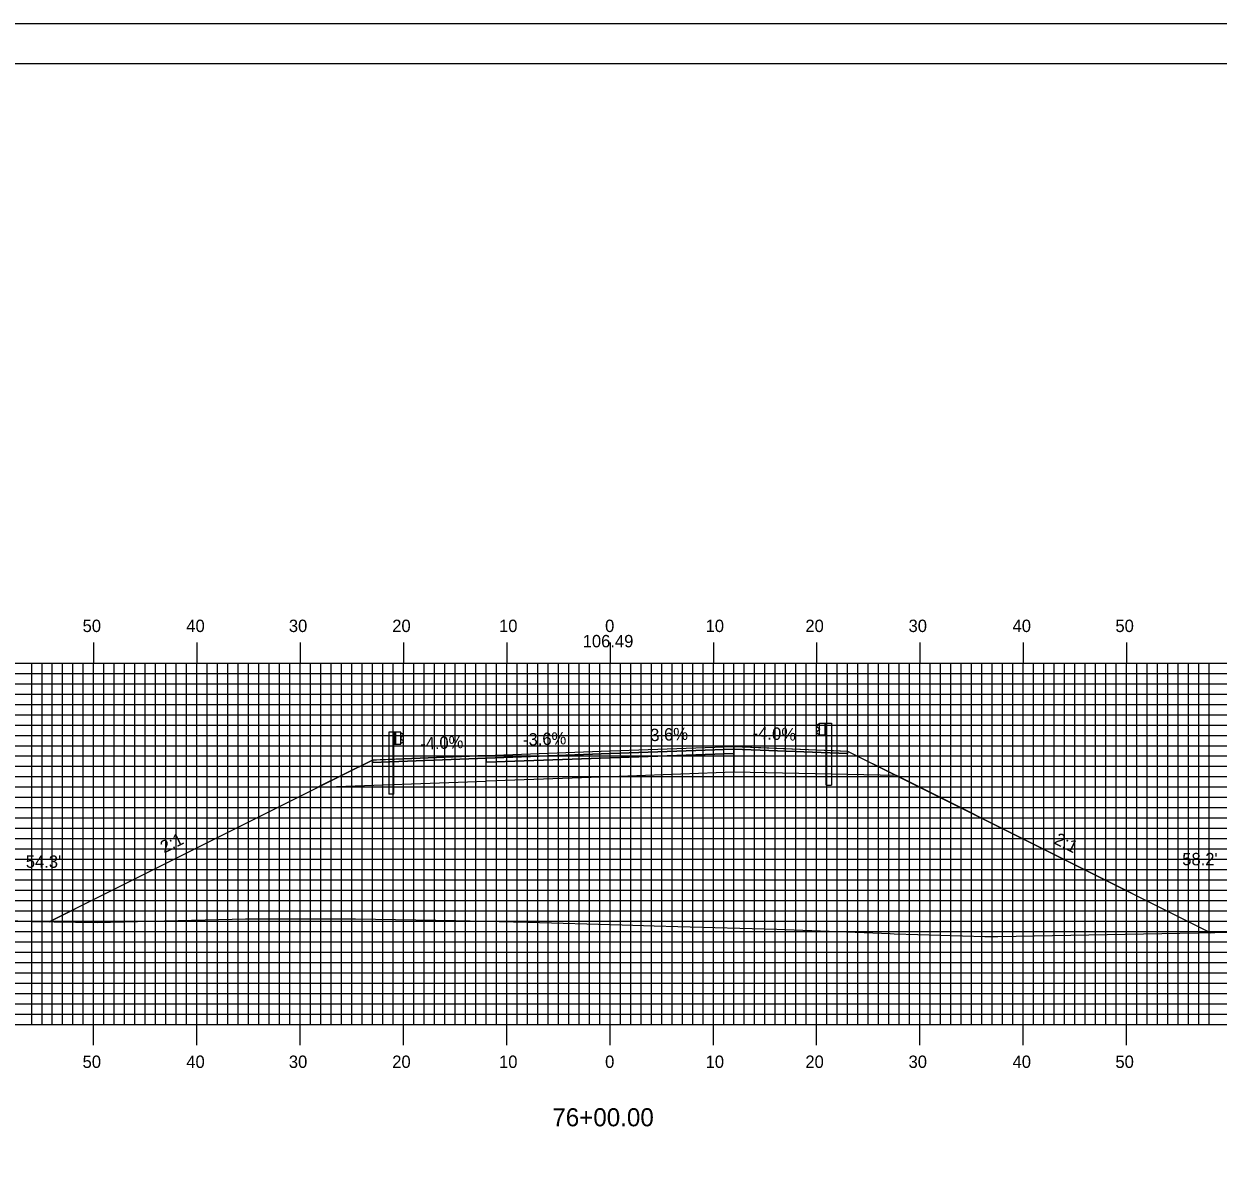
# Model space of a CAD drawing. Extents: x 1761397 to 1761741, y 442591 to 442811.
# Drawn here: x 1761506.5 to 1761622.1, y 442700.5 to 442810.5 of the extents above; entities that cross this region are included whole.
import ezdxf

# ---------------------------------------------------------------- set-up
doc = ezdxf.new("R2010")
doc.units = 0
for name, color, linetype in [('ANNOTATION', 7, 'Continuous'), ('BORDER', 7, 'Continuous'), ('D_Guardrail_Beam_Lt', 7, 'Continuous'), ('D_Guardrail_Beam_Rt', 7, 'Continuous'), ('D_Roadway_Centerline', 7, 'Continuous'), ('D_Roadway_Centerline_Text', 7, 'Continuous'), ('D_Roadway_Edge_Shoulder', 7, 'Continuous'), ('D_Roadway_Edge_TW', 7, 'Continuous'), ('D_Roadway_Pavement', 7, 'Continuous'), ('D_Roadway_SlopeLines', 7, 'Continuous'), ('D_Roadway_SubGrade', 7, 'Continuous'), ('D_Text_Standard', 7, 'Continuous'), ('H_V ANNOTATION', 7, 'Continuous'), ('MAJOR', 7, 'Continuous'), ('MINOR', 7, 'Continuous'), ('PLOT BOUNDARY', 7, 'Continuous'), ('S_Roadway_Centerline', 7, 'Continuous')]:
    doc.layers.add(name, color=color, linetype=linetype)

msp = doc.modelspace()

# ---------------------------------------------------------------- linework, layer by layer
at = {"layer": 'BORDER'}
msp.add_lwpolyline([(1761413.64, 442596.67), (1761733.64, 442596.67), (1761733.64, 442806.67), (1761413.64, 442806.67)], close=True, dxfattribs=at)
at = {"layer": 'D_Guardrail_Beam_Lt'}
for p, q in [((1761541.81, 442741.99), (1761541.81, 442735.99)), ((1761542.28, 442741.99), (1761541.81, 442741.99)), ((1761542.97, 442741.99), (1761542.28, 442741.99)), ((1761542.28, 442741.99), (1761542.28, 442740.82)), ((1761542.34, 442741.99), (1761542.34, 442740.82)), ((1761542.45, 442741.99), (1761542.45, 442740.82)), ((1761542.97, 442740.82), (1761542.97, 442741.99)), ((1761542.97, 442741.9), (1761543.04, 442741.89)), ((1761542.97, 442741.44), (1761542.97, 442741.37)), ((1761543.2, 442741.64), (1761543.01, 442741.5)), ((1761543.01, 442741.3), (1761543.2, 442741.17)), ((1761543.06, 442741.88), (1761543.2, 442741.78)), ((1761542.28, 442740.82), (1761542.97, 442740.82)), ((1761542.3, 442735.99), (1761542.3, 442740.82)), ((1761543.04, 442740.92), (1761542.97, 442740.9)), ((1761543.2, 442741.02), (1761543.06, 442740.92)), ((1761542.3, 442735.99), (1761541.81, 442735.99))]:
    msp.add_line(p, q, dxfattribs=at)
for centre, major_axis, start_param, end_param in [((1761543.05, 442741.44), (-0.0789, 0), 5.323254, 6.283185), ((1761543.05, 442741.37), (-0.0789, 0), 6.283185, 7.243116), ((1761543.03, 442741.85), (0.0417, 0), 0.959931, 1.376053), ((1761543.15, 442741.71), (0.0877, 0), 5.323254, 7.243116), ((1761543.15, 442741.1), (0.0877, 0), 5.323254, 7.243116), ((1761543.03, 442740.96), (0.0417, 0), 4.907132, 5.323254)]:
    msp.add_ellipse(centre, major_axis=major_axis, ratio=0.995501, start_param=start_param, end_param=end_param, dxfattribs=at)
at = {"layer": 'D_Guardrail_Beam_Rt'}
for p, q in [((1761583.42, 442742.75), (1761583.28, 442742.65)), ((1761583.28, 442742.5), (1761583.47, 442742.37)), ((1761583.51, 442742.77), (1761583.44, 442742.75)), ((1761583.51, 442742.85), (1761584.2, 442742.85)), ((1761583.51, 442741.68), (1761583.51, 442742.85)), ((1761584.03, 442742.85), (1761584.03, 442741.68)), ((1761584.14, 442742.85), (1761584.14, 442741.68)), ((1761584.2, 442742.85), (1761584.67, 442742.85)), ((1761584.2, 442742.85), (1761584.2, 442741.68)), ((1761584.67, 442742.85), (1761584.67, 442736.85)), ((1761583.47, 442742.17), (1761583.28, 442742.03)), ((1761583.28, 442741.89), (1761583.42, 442741.79)), ((1761583.44, 442741.78), (1761583.51, 442741.77)), ((1761583.51, 442742.3), (1761583.51, 442742.23)), ((1761584.2, 442741.68), (1761583.51, 442741.68)), ((1761584.18, 442736.85), (1761584.18, 442741.68)), ((1761584.18, 442736.85), (1761584.67, 442736.85))]:
    msp.add_line(p, q, dxfattribs=at)
for centre, major_axis, start_param, end_param in [((1761583.33, 442742.57), (-0.0877, 0), 5.323254, 7.243116), ((1761583.44, 442742.71), (-0.0417, 0), 4.907132, 5.323254), ((1761583.43, 442742.3), (0.0789, 0), 0, 0.959931), ((1761583.33, 442741.96), (-0.0877, 0), 5.323254, 7.243116), ((1761583.44, 442741.82), (-0.0417, 0), 0.959931, 1.376053), ((1761583.43, 442742.23), (0.0789, 0), 5.323254, 6.283185)]:
    msp.add_ellipse(centre, major_axis=major_axis, ratio=0.995501, start_param=start_param, end_param=end_param, dxfattribs=at)
at = {"layer": 'D_Roadway_Centerline'}
msp.add_lwpolyline([(1761508.92, 442723.62), (1761508.92, 442723.62), (1761514.06, 442726.19), (1761534.93, 442736.63), (1761534.95, 442736.64), (1761534.95, 442736.64), (1761540.24, 442739.28), (1761540.64, 442739.3), (1761543.24, 442739.4), (1761543.24, 442739.4), (1761551.24, 442739.72), (1761563.24, 442740.16), (1761563.24, 442740.16), (1761575.24, 442740.59), (1761577.85, 442740.48), (1761583.23, 442740.27), (1761583.24, 442740.27), (1761584.88, 442740.2), (1761586.24, 442740.15), (1761590.99, 442737.77), (1761590.99, 442737.77), (1761591, 442737.77), (1761621.41, 442722.56)], dxfattribs=at)
at = {"layer": 'D_Roadway_Edge_Shoulder'}
for points in [[(1761575.24, 442740.59), (1761583.24, 442740.27), (1761583.24, 442740.27), (1761586.24, 442740.15), (1761586.24, 442739.9), (1761575.24, 442740.34)], [(1761551.24, 442739.72), (1761543.24, 442739.4), (1761543.24, 442739.4), (1761540.24, 442739.28), (1761540.24, 442739.03), (1761551.24, 442739.47)]]:
    msp.add_lwpolyline(points, close=True, dxfattribs=at)
at = {"layer": 'D_Roadway_Edge_TW'}
msp.add_lwpolyline([(1761551.24, 442739.47), (1761551.24, 442739.72), (1761563.24, 442740.16), (1761575.24, 442740.59), (1761575.24, 442740.34), (1761563.24, 442739.91)], close=True, dxfattribs=at)
at = {"layer": 'D_Roadway_Pavement'}
msp.add_lwpolyline([(1761551.24, 442739.06), (1761551.24, 442739.47), (1761563.24, 442739.91), (1761575.24, 442740.34), (1761575.24, 442739.92), (1761563.24, 442739.49)], close=True, dxfattribs=at)
for points in [[(1761575.24, 442740.34), (1761575.24, 442739.92)], [(1761551.24, 442739.47), (1761551.24, 442739.06)]]:
    msp.add_lwpolyline(points, dxfattribs=at)
at = {"layer": 'D_Roadway_SlopeLines'}
for points in [[(1761586.24, 442740.15), (1761621.41, 442722.56)], [(1761540.24, 442739.28), (1761508.92, 442723.62)]]:
    msp.add_lwpolyline(points, dxfattribs=at)
at = {"layer": 'D_Roadway_SubGrade'}
for points in [[(1761551.24, 442737.22), (1761551.24, 442739.47), (1761551.24, 442739.06), (1761563.24, 442739.49), (1761575.24, 442739.92), (1761575.24, 442740.34), (1761575.24, 442738.09), (1761563.24, 442737.66)], [(1761575.24, 442739.92), (1761575.24, 442740.34), (1761586.24, 442739.9), (1761586.24, 442740.15), (1761590.99, 442737.77), (1761575.24, 442738.09)], [(1761551.24, 442739.06), (1761551.24, 442739.47), (1761540.24, 442739.03), (1761540.24, 442739.28), (1761534.95, 442736.64), (1761551.24, 442737.22)]]:
    msp.add_lwpolyline(points, close=True, dxfattribs=at)
at = {"layer": 'MAJOR'}
for p, q in [((1761513.24, 442750.67), (1761513.24, 442748.67)), ((1761523.24, 442750.67), (1761523.24, 442748.67)), ((1761533.24, 442750.67), (1761533.24, 442748.67)), ((1761543.24, 442750.67), (1761543.24, 442748.67)), ((1761553.24, 442750.67), (1761553.24, 442748.67)), ((1761563.24, 442750.67), (1761563.24, 442748.67)), ((1761573.24, 442750.67), (1761573.24, 442748.67)), ((1761583.24, 442750.67), (1761583.24, 442748.67)), ((1761593.24, 442750.67), (1761593.24, 442748.67)), ((1761603.24, 442750.67), (1761603.24, 442748.67)), ((1761613.24, 442750.67), (1761613.24, 442748.67)), ((1761423.24, 442748.67), (1761703.24, 442748.67)), ((1761423.24, 442748.67), (1761703.24, 442748.67)), ((1761513.24, 442713.67), (1761513.24, 442748.67)), ((1761523.24, 442713.67), (1761523.24, 442748.67)), ((1761533.24, 442713.67), (1761533.24, 442748.67)), ((1761543.24, 442713.67), (1761543.24, 442748.67)), ((1761553.24, 442713.67), (1761553.24, 442748.67)), ((1761563.24, 442713.67), (1761563.24, 442748.67)), ((1761573.24, 442713.67), (1761573.24, 442748.67)), ((1761583.24, 442713.67), (1761583.24, 442748.67)), ((1761593.24, 442713.67), (1761593.24, 442748.67)), ((1761603.24, 442713.67), (1761603.24, 442748.67)), ((1761613.24, 442713.67), (1761613.24, 442748.67)), ((1761423.24, 442743.67), (1761703.24, 442743.67)), ((1761423.24, 442738.67), (1761703.24, 442738.67)), ((1761423.24, 442733.67), (1761703.24, 442733.67)), ((1761423.24, 442728.67), (1761703.24, 442728.67)), ((1761423.24, 442723.67), (1761703.24, 442723.67)), ((1761423.24, 442718.67), (1761703.24, 442718.67)), ((1761423.24, 442713.67), (1761703.24, 442713.67)), ((1761423.24, 442713.67), (1761703.24, 442713.67)), ((1761513.24, 442711.66), (1761513.24, 442713.67)), ((1761523.24, 442711.66), (1761523.24, 442713.67)), ((1761533.24, 442711.66), (1761533.24, 442713.67)), ((1761543.24, 442711.66), (1761543.24, 442713.67)), ((1761553.24, 442711.66), (1761553.24, 442713.67)), ((1761563.24, 442711.66), (1761563.24, 442713.67)), ((1761573.24, 442711.66), (1761573.24, 442713.67)), ((1761583.24, 442711.66), (1761583.24, 442713.67)), ((1761593.24, 442711.66), (1761593.24, 442713.67)), ((1761603.24, 442711.66), (1761603.24, 442713.67)), ((1761613.24, 442711.66), (1761613.24, 442713.67))]:
    msp.add_line(p, q, dxfattribs=at)
at = {"layer": 'MINOR'}
for p, q in [((1761507.24, 442713.67), (1761507.24, 442748.67)), ((1761508.24, 442713.67), (1761508.24, 442748.67)), ((1761509.24, 442713.67), (1761509.24, 442748.67)), ((1761510.24, 442713.67), (1761510.24, 442748.67)), ((1761511.24, 442713.67), (1761511.24, 442748.67)), ((1761512.24, 442713.67), (1761512.24, 442748.67)), ((1761514.24, 442713.67), (1761514.24, 442748.67)), ((1761515.24, 442713.67), (1761515.24, 442748.67)), ((1761516.24, 442713.67), (1761516.24, 442748.67)), ((1761517.24, 442713.67), (1761517.24, 442748.67)), ((1761518.24, 442713.67), (1761518.24, 442748.67)), ((1761519.24, 442713.67), (1761519.24, 442748.67)), ((1761520.24, 442713.67), (1761520.24, 442748.67)), ((1761521.24, 442713.67), (1761521.24, 442748.67)), ((1761522.24, 442713.67), (1761522.24, 442748.67)), ((1761524.24, 442713.67), (1761524.24, 442748.67)), ((1761525.24, 442713.67), (1761525.24, 442748.67)), ((1761526.24, 442713.67), (1761526.24, 442748.67)), ((1761527.24, 442713.67), (1761527.24, 442748.67)), ((1761528.24, 442713.67), (1761528.24, 442748.67)), ((1761529.24, 442713.67), (1761529.24, 442748.67)), ((1761530.24, 442713.67), (1761530.24, 442748.67)), ((1761531.24, 442713.67), (1761531.24, 442748.67)), ((1761532.24, 442713.67), (1761532.24, 442748.67)), ((1761534.24, 442713.67), (1761534.24, 442748.67)), ((1761535.24, 442713.67), (1761535.24, 442748.67)), ((1761536.24, 442713.67), (1761536.24, 442748.67)), ((1761537.24, 442713.67), (1761537.24, 442748.67)), ((1761538.24, 442713.67), (1761538.24, 442748.67)), ((1761539.24, 442713.67), (1761539.24, 442748.67)), ((1761540.24, 442713.67), (1761540.24, 442748.67)), ((1761541.24, 442713.67), (1761541.24, 442748.67)), ((1761542.24, 442713.67), (1761542.24, 442748.67)), ((1761544.24, 442713.67), (1761544.24, 442748.67)), ((1761545.24, 442713.67), (1761545.24, 442748.67)), ((1761546.24, 442713.67), (1761546.24, 442748.67)), ((1761547.24, 442713.67), (1761547.24, 442748.67)), ((1761548.24, 442713.67), (1761548.24, 442748.67)), ((1761549.24, 442713.67), (1761549.24, 442748.67)), ((1761550.24, 442713.67), (1761550.24, 442748.67)), ((1761551.24, 442713.67), (1761551.24, 442748.67)), ((1761552.24, 442713.67), (1761552.24, 442748.67)), ((1761554.24, 442713.67), (1761554.24, 442748.67)), ((1761555.24, 442713.67), (1761555.24, 442748.67)), ((1761556.24, 442713.67), (1761556.24, 442748.67)), ((1761557.24, 442713.67), (1761557.24, 442748.67)), ((1761558.24, 442713.67), (1761558.24, 442748.67)), ((1761559.24, 442713.67), (1761559.24, 442748.67)), ((1761560.24, 442713.67), (1761560.24, 442748.67)), ((1761561.24, 442713.67), (1761561.24, 442748.67)), ((1761562.24, 442713.67), (1761562.24, 442748.67)), ((1761564.24, 442713.67), (1761564.24, 442748.67)), ((1761565.24, 442713.67), (1761565.24, 442748.67)), ((1761566.24, 442713.67), (1761566.24, 442748.67)), ((1761567.24, 442713.67), (1761567.24, 442748.67)), ((1761568.24, 442713.67), (1761568.24, 442748.67)), ((1761569.24, 442713.67), (1761569.24, 442748.67)), ((1761570.24, 442713.67), (1761570.24, 442748.67)), ((1761571.24, 442713.67), (1761571.24, 442748.67)), ((1761572.24, 442713.67), (1761572.24, 442748.67)), ((1761574.24, 442713.67), (1761574.24, 442748.67)), ((1761575.24, 442713.67), (1761575.24, 442748.67)), ((1761576.24, 442713.67), (1761576.24, 442748.67)), ((1761577.24, 442713.67), (1761577.24, 442748.67)), ((1761578.24, 442713.67), (1761578.24, 442748.67)), ((1761579.24, 442713.67), (1761579.24, 442748.67)), ((1761580.24, 442713.67), (1761580.24, 442748.67)), ((1761581.24, 442713.67), (1761581.24, 442748.67)), ((1761582.24, 442713.67), (1761582.24, 442748.67)), ((1761584.24, 442713.67), (1761584.24, 442748.67)), ((1761585.24, 442713.67), (1761585.24, 442748.67)), ((1761586.24, 442713.67), (1761586.24, 442748.67)), ((1761587.24, 442713.67), (1761587.24, 442748.67)), ((1761588.24, 442713.67), (1761588.24, 442748.67)), ((1761589.24, 442713.67), (1761589.24, 442748.67)), ((1761590.24, 442713.67), (1761590.24, 442748.67)), ((1761591.24, 442713.67), (1761591.24, 442748.67)), ((1761592.24, 442713.67), (1761592.24, 442748.67)), ((1761594.24, 442713.67), (1761594.24, 442748.67)), ((1761595.24, 442713.67), (1761595.24, 442748.67)), ((1761596.24, 442713.67), (1761596.24, 442748.67)), ((1761597.24, 442713.67), (1761597.24, 442748.67)), ((1761598.24, 442713.67), (1761598.24, 442748.67)), ((1761599.24, 442713.67), (1761599.24, 442748.67)), ((1761600.24, 442713.67), (1761600.24, 442748.67)), ((1761601.24, 442713.67), (1761601.24, 442748.67)), ((1761602.24, 442713.67), (1761602.24, 442748.67)), ((1761604.24, 442713.67), (1761604.24, 442748.67)), ((1761605.24, 442713.67), (1761605.24, 442748.67)), ((1761606.24, 442713.67), (1761606.24, 442748.67)), ((1761607.24, 442713.67), (1761607.24, 442748.67)), ((1761608.24, 442713.67), (1761608.24, 442748.67)), ((1761609.24, 442713.67), (1761609.24, 442748.67)), ((1761610.24, 442713.67), (1761610.24, 442748.67)), ((1761611.24, 442713.67), (1761611.24, 442748.67)), ((1761612.24, 442713.67), (1761612.24, 442748.67)), ((1761614.24, 442713.67), (1761614.24, 442748.67)), ((1761615.24, 442713.67), (1761615.24, 442748.67)), ((1761616.24, 442713.67), (1761616.24, 442748.67)), ((1761617.24, 442713.67), (1761617.24, 442748.67)), ((1761618.24, 442713.67), (1761618.24, 442748.67)), ((1761619.24, 442713.67), (1761619.24, 442748.67)), ((1761620.24, 442713.67), (1761620.24, 442748.67)), ((1761621.24, 442713.67), (1761621.24, 442748.67)), ((1761423.24, 442747.67), (1761703.24, 442747.67)), ((1761423.24, 442746.67), (1761703.24, 442746.67)), ((1761423.24, 442745.67), (1761703.24, 442745.67)), ((1761423.24, 442744.67), (1761703.24, 442744.67)), ((1761423.24, 442742.67), (1761703.24, 442742.67)), ((1761423.24, 442741.67), (1761703.24, 442741.67)), ((1761423.24, 442740.67), (1761703.24, 442740.67)), ((1761423.24, 442739.67), (1761703.24, 442739.67)), ((1761423.24, 442737.67), (1761703.24, 442737.67)), ((1761423.24, 442736.67), (1761703.24, 442736.67)), ((1761423.24, 442735.67), (1761703.24, 442735.67)), ((1761423.24, 442734.67), (1761703.24, 442734.67)), ((1761423.24, 442732.67), (1761703.24, 442732.67)), ((1761423.24, 442731.67), (1761703.24, 442731.67)), ((1761423.24, 442730.67), (1761703.24, 442730.67)), ((1761423.24, 442729.67), (1761703.24, 442729.67)), ((1761423.24, 442727.67), (1761703.24, 442727.67)), ((1761423.24, 442726.67), (1761703.24, 442726.67)), ((1761423.24, 442725.67), (1761703.24, 442725.67)), ((1761423.24, 442724.67), (1761703.24, 442724.67)), ((1761423.24, 442722.67), (1761703.24, 442722.67)), ((1761423.24, 442721.67), (1761703.24, 442721.67)), ((1761423.24, 442720.67), (1761703.24, 442720.67)), ((1761423.24, 442719.67), (1761703.24, 442719.67)), ((1761423.24, 442717.67), (1761703.24, 442717.67)), ((1761423.24, 442716.67), (1761703.24, 442716.67)), ((1761423.24, 442715.67), (1761703.24, 442715.67)), ((1761423.24, 442714.67), (1761703.24, 442714.67))]:
    msp.add_line(p, q, dxfattribs=at)
at = {"layer": 'PLOT BOUNDARY'}
msp.add_lwpolyline([(1761397.45, 442590.55), (1761737.45, 442590.55), (1761737.45, 442810.55), (1761397.45, 442810.55)], close=True, dxfattribs=at)
at = {"layer": 'S_Roadway_Centerline'}
msp.add_lwpolyline([(1761498.04, 442724.08), (1761507.32, 442723.65), (1761513.57, 442723.54), (1761527.95, 442723.92), (1761538.6, 442723.9), (1761548.3, 442723.74), (1761555.27, 442723.58), (1761564.4, 442723.31), (1761567.51, 442723.22), (1761569.81, 442723.17), (1761579.4, 442722.92), (1761590.35, 442722.47), (1761590.76, 442722.45), (1761593.04, 442722.38), (1761599.54, 442722.18), (1761600.07, 442722.21), (1761600.78, 442722.18), (1761620.18, 442722.54), (1761626.71, 442722.68)], dxfattribs=at)

# ---------------------------------------------------------------- texts
at = {"layer": 'ANNOTATION'}
for s, rotation, p in [('3.6%', 2.0617, (1761567.15, 442741.1)), ('-4.0%', 357.7093, (1761577.03, 442741.32)), ('-4.0%', 2.2907, (1761544.87, 442740.27)), ('-3.6%', 2.0616, (1761554.83, 442740.65)), ('2:1', 26.5641, (1761520.07, 442730.23)), ('2:1', 333.4344, (1761606.14, 442731.23))]:
    msp.add_text(s, height=1.2, rotation=rotation, dxfattribs=at).set_placement(p)
at = {"layer": 'D_Roadway_Centerline'}
for s, p in [('C', (1761563.23, 442740.16)), ('L', (1761563.24, 442740.15))]:
    msp.add_text(s, height=0.0146, dxfattribs=at).set_placement(p)
at = {"layer": 'D_Roadway_Centerline_Text'}
msp.add_text('106.49', height=1.2, dxfattribs=at).set_placement((1761560.59, 442750.19))
at = {"layer": 'D_Text_Standard'}
for s, p in [("54.3'", (1761506.67, 442728.85)), ("58.2'", (1761618.64, 442729.09))]:
    msp.add_text(s, height=1.2, dxfattribs=at).set_placement(p)
at = {"layer": 'H_V ANNOTATION'}
for s, height, p in [('50', 1.2, (1761512.17, 442751.67)), ('40', 1.2, (1761522.21, 442751.67)), ('30', 1.2, (1761532.14, 442751.67)), ('20', 1.2, (1761542.15, 442751.67)), ('10', 1.2, (1761552.49, 442751.67)), ('0', 1.2, (1761562.76, 442751.67)), ('10', 1.2, (1761572.49, 442751.67)), ('20', 1.2, (1761582.15, 442751.67)), ('30', 1.2, (1761592.14, 442751.67)), ('40', 1.2, (1761602.21, 442751.67)), ('50', 1.2, (1761612.17, 442751.67)), ('50', 1.2, (1761512.17, 442709.47)), ('40', 1.2, (1761522.21, 442709.47)), ('30', 1.2, (1761532.14, 442709.47)), ('20', 1.2, (1761542.15, 442709.47)), ('10', 1.2, (1761552.49, 442709.47)), ('0', 1.2, (1761562.76, 442709.47)), ('10', 1.2, (1761572.49, 442709.47)), ('20', 1.2, (1761582.15, 442709.47)), ('30', 1.2, (1761592.14, 442709.47)), ('40', 1.2, (1761602.21, 442709.47)), ('50', 1.2, (1761612.17, 442709.47)), ('76+00.00', 1.75, (1761557.65, 442703.82))]:
    msp.add_text(s, height=height, dxfattribs=at).set_placement(p)

doc.saveas('drawing.dxf')
